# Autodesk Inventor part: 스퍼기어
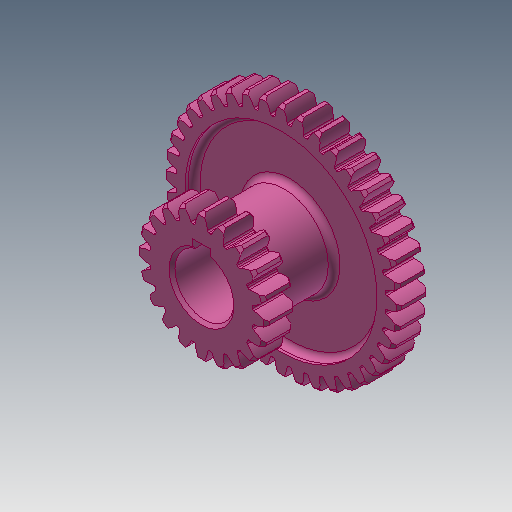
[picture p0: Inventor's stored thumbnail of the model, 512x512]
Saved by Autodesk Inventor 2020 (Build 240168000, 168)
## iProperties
Created: 2015-09
Part Number: 스퍼기어
Material: 강철, 연강
Document SubType Name: Modeling
Designer: mduedu
Density: 7.86 g/cm^3
Mass: 345.726 g
Surface Area: 225.641 cm^2
Volume: 43.9855 cm^3
Appearance: 분홍색
Author: mduedu
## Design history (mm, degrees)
sketch "스케치1"
  geometry: C1 r 38 at (0, 0); C2 r 40 at (0, 0); C3 r 35.5 at (0, 0); 1 further point
  constraints: 3 centre point, 3 coincident
  dimensions: "d0" = 76 diameter of C1; "d2" = 2 radial gap between concentric circles of C2 C1; "d3" = 71 diameter of C3 (computed from d0)
extrude "돌출1" new body sketch "스케치1" stored distance "d4" = 10; taper "d5" = 0 deg
sketch "스케치2"
  geometry: L1 (0, 35.5)-(0, -35.5); L2 (0, 0)-(40, 0); L3 (0, 0.57)-(39.996, 0.57); L4 (0, 1.57)-(39.969, 1.57); L5 (0, 2.07)-(39.946, 2.07); A1 r 35.5 centre (0, 0) between (0, 35.5) and (0, -35.5) reference; A2 r 40 centre (0, 0) between (40, 0) and (39.946, 2.07) reference; A3 r 9.234 centre (34.93, -7.149) between (39.996, 0.57) and (35.44, 2.07); A4 r 9.234 centre (34.93, 7.149) between (35.44, -2.07) and (39.996, -0.57); A5 r 40 centre (0, 0) between (39.996, -0.57) and (39.996, 0.57); A6 r 35.5 centre (0, 0) between (35.44, -2.07) and (35.44, 2.07); 4 further points
  constraints: 16 point on circle, 10 end point, 6 point on line, 4 centre point, 3 coincident, 3 parallel, 3 symmetric about line, 2 midpoint, 1 perpendicular, 1 vertical, 3 other
  dimensions: "d6" = 0.5 distance between parallel lines of L4 L5; "d8" = 1 distance between parallel lines of L3 L4; "d9" = 1.57 distance between parallel lines of L2 L4
extrude "돌출2" join sketch "스케치2" distance "d10" = 5; taper "d12" = 0 deg; dims "d11" = 5, "d13" = 0
fillet "모깎기1" dims "d17" = 0.5
chamfer "모따기1" distance "d21" = 1; stored, may be unused: second distance "d22" = 2, angle "d23" = 45 deg
sketch "스케치3"
  geometry: C1 r 32.5 at (0, 0); C2 r 15 at (0, 0); 1 further point
  constraints: 2 centre point, 2 coincident
  dimensions: "d27" = 65 diameter of C1; "d28" = 30 diameter of C2
extrude "돌출3" cut sketch "스케치3" distance "d29" = 3; taper "d30" = 0 deg
fillet "모깎기2" dims "d31" = 2
node "작업 평면2"
  node "작업 평면1"
sketch "스케치4"
  geometry: C1 r 15 at (0, 0) reference; 1 further point
extrude "돌출4" join sketch "스케치4" stored distance "d34" = 3; taper "d35" = 0 deg
sketch "스케치5"
  geometry: C1 r 17.5 at (0, 0); C2 r 20 at (0, 0); C3 r 22 at (0, 0); 1 further point
  constraints: 3 centre point, 3 coincident
  dimensions: "d36" = 40 diameter of C2; "d38" = 2 radial gap between concentric circles of C2 C3; "d39" = 35 diameter of C1 (= d36 - 2.5 x d38)
extrude "돌출6" join sketch "스케치5" distance "d46" = 10; taper "d47" = 0 deg
sketch "스케치6"
  geometry: L1 (0, 0)-(0, 22); L2 (-17.5, 0)-(17.5, 0); L3 (-0.57, 0)-(-0.57, 21.993); L4 (-1.57, 0)-(-1.57, 21.944); L5 (-2.07, 0)-(-2.07, 21.902); A1 r 22 centre (0, 0) between (0, 22) and (-0.57, 21.993) reference; A2 r 17.5 centre (0, 0) between (-17.5, 0) and (17.5, 0) reference; A3 r 9.431 centre (7.348, 16.868) between (-0.57, 21.993) and (-2.07, 17.377); A4 r 9.431 centre (-7.348, 16.868) between (2.07, 17.377) and (0.57, 21.993); A5 r 17.5 centre (0, 0) between (2.07, 17.377) and (-2.07, 17.377); A6 r 22 centre (0, 0) between (0.57, 21.993) and (-0.57, 21.993); 4 further points
  constraints: 16 point on circle, 10 end point, 5 point on line, 4 centre point, 3 coincident, 3 symmetric about line, 2 parallel, 2 perpendicular, 1 midpoint, 1 vertical, 3 other
  dimensions: "d40" = 0.5 distance between parallel lines of L4 L5; "d42" = 1 distance between parallel lines of L3 L4; "d43" = 1.57 distance between parallel lines of L1 L4
extrude "돌출5" join sketch "스케치6" distance "d44" = 10; taper "d45" = 0 deg
fillet "모깎기3" dims "d48" = 0.5
chamfer "모따기2" distance "d49" = 1; stored, may be unused: second distance "d50" = 2, angle "d51" = 45 deg
sketch "스케치7"
  geometry: C1 r 10 at (0, 0); 1 further point
  constraints: 1 centre point, 1 coincident
  dimensions: "d55" = 20 diameter of C1
extrude "돌출7" cut sketch "스케치7" extent not by distance; stored distance "d56" = 10; taper "d57" = 0 deg
sketch "스케치8"
  geometry: L1 (-9.539, -3)-(-12.8, -3); L2 (-12.8, -3)-(-12.8, 3); L3 (-12.8, 3)-(-9.539, 3); L4 (-9.539, 3)-(-9.539, -3); A1 r 10 centre (0, 0) between (-9.539, -3) and (-9.539, 3) reference; 2 further points
  constraints: 8 end point, 3 point on circle, 2 parallel, 1 horizontal, 1 horizontal alignment, 1 perpendicular
  dimensions: "d58" = 6 distance of L1.end L2.end; "d60" = 22.8 distance from line of point (10, 0) L2
extrude "돌출8" cut sketch "스케치8" extent not by distance; stored distance "d61" = 10; taper "d62" = 0 deg
chamfer "모따기3" distance "d63" = 1; stored, may be unused: second distance "d64" = 2, angle "d65" = 45 deg
fillet "모깎기4" dims "d66" = 2
node "솔리드1"
pattern_circular "원형 패턴3" dims angle "d25" = 360 deg
mirror "대칭1"
pattern_circular "원형 패턴4" dims angle "d53" = 360 deg
other parameters: "d32" = 5, "d33" = 42
